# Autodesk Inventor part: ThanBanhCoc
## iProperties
Created: 2010-09
Part Number: ThanBanhCoc
Document SubType Name: Modeling
Designer: nguyenducthang
Density: 1 g/cm^3
Mass: 7.01593 g
Surface Area: 23.5398 cm^2
Volume: 7.01593 cm^3
Author: nguyenducthang
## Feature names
1. Extrusion3
2. Extrusion4
